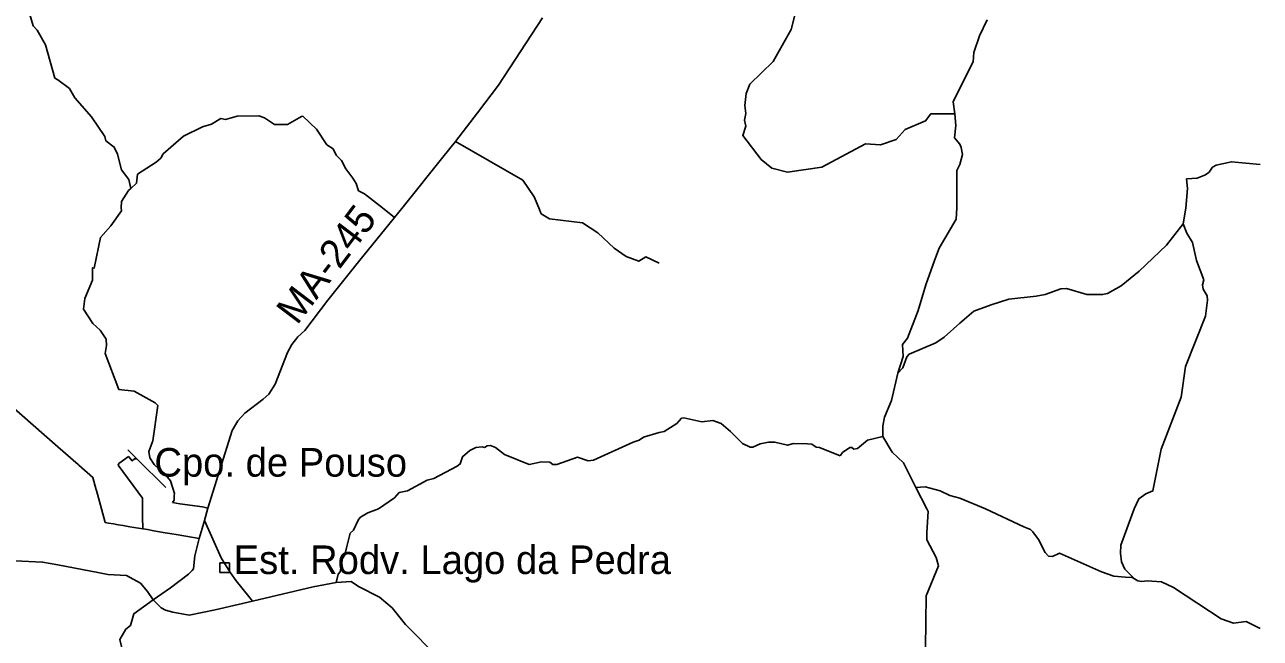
# Model space of a CAD drawing. Extents: x 332 to 501, y 9447 to 9559.
# Drawn here: x 483.56 to 500, y 9494.28 to 9502.44 of the extents above; entities that cross this region are included whole.
import ezdxf

# ---------------------------------------------------------------- set-up
doc = ezdxf.new("R2010")
doc.units = 0
for name, color, linetype in [('Level 1', 7, 'Continuous'), ('Level 13', 7, 'Continuous'), ('Level 19', 7, 'Continuous'), ('Level 2', 7, 'Continuous'), ('Level 31', 7, 'Continuous'), ('Level 4', 7, 'Continuous'), ('Level 5', 7, 'Continuous'), ('Level 51', 7, 'Continuous'), ('Level 6', 7, 'Continuous'), ('Level 8', 7, 'Continuous')]:
    doc.layers.add(name, color=color, linetype=linetype)

msp = doc.modelspace()

# ---------------------------------------------------------------- linework, layer by layer
at = {"layer": 'Level 1'}
for points in [[(485.0499, 9496.6649), (484.9306, 9496.7822)], [(485.4367, 9496.2847), (485.0499, 9496.6649)]]:
    msp.add_lwpolyline(points, dxfattribs=at)
at = {"layer": 'Level 2'}
for points in [[(490.4495, 9502.5277), (489.864, 9501.6325), (489.5831, 9501.2645)], [(489.5831, 9501.2645), (489.2899, 9500.8829)], [(489.2899, 9500.8829), (489.1226, 9500.6734)], [(489.1226, 9500.6734), (488.5953, 9500.0133)], [(484, 9496.8247), (483.1916, 9497.5294), (483.1148, 9497.7406), (483.0763, 9497.9134), (483.1084, 9498.2847), (482.7391, 9498.8538), (482.6815, 9498.9947), (482.5855, 9499.1612), (482.2526, 9499.648), (481.8249, 9499.9937)], [(488.5953, 9500.0133), (488.481, 9499.8732)], [(488.481, 9499.8732), (488, 9499.2833)], [(488, 9499.2833), (487.5929, 9498.7736)], [(487.5929, 9498.7736), (487.2845, 9498.3721), (487.1935, 9498.2871), (487.1146, 9498.1838), (487.0539, 9498.0763), (486.89, 9497.6573), (486.805, 9497.5237), (486.7295, 9497.4557)], [(486.7295, 9497.4557), (486.4886, 9497.2719)], [(486.4886, 9497.2719), (486.3934, 9497.1687), (486.3172, 9497.0424), (486.1558, 9496.5182)], [(484.2698, 9496.5875), (484, 9496.8247)], [(484.2779, 9496.5804), (484.2698, 9496.5875)], [(484.5109, 9496.2514), (484.4653, 9496.4157), (484.2779, 9496.5804)], [(485.1268, 9496.0355), (485.126, 9496.143), (484.803, 9496.5781)], [(486.1558, 9496.5181), (485.9973, 9496.0064)], [(486.1558, 9496.5182), (486.1558, 9496.5181)], [(484.5137, 9496.2414), (484.5109, 9496.2514)], [(484.5807, 9496), (484.5137, 9496.2414)], [(485.1271, 9496), (485.1268, 9496.0355)], [(484.6314, 9495.8174), (484.5807, 9496)], [(485.1272, 9495.9871), (485.1271, 9496)], [(485.1279, 9495.898), (485.1272, 9495.9871)], [(485.1293, 9495.7329), (485.1279, 9495.898)], [(485.9973, 9496.0064), (485.9509, 9495.8445)], [(484.6314, 9495.8174), (484.6747, 9495.8089)], [(484.6747, 9495.8089), (484.7381, 9495.7981)], [(484.7381, 9495.7981), (484.802, 9495.7873)], [(484.802, 9495.7873), (484.8702, 9495.7757)], [(484.8702, 9495.7757), (484.9557, 9495.7612)], [(484.9557, 9495.7612), (485.1293, 9495.7329)], [(485.1293, 9495.7329), (485.1929, 9495.7225)], [(485.1929, 9495.7225), (485.2768, 9495.7068)], [(485.2768, 9495.7068), (485.4283, 9495.6808)], [(485.9196, 9495.738), (485.8813, 9495.6038)], [(485.9509, 9495.8445), (485.9196, 9495.738)], [(485.4283, 9495.6808), (485.4902, 9495.6703)], [(485.4902, 9495.6703), (485.6003, 9495.6516)], [(485.6003, 9495.6516), (485.8813, 9495.6038)], [(485.8813, 9495.6038), (485.8219, 9495.3743), (485.8058, 9495.2011), (485.789, 9495.1806)], [(484, 9495.2529), (483.7972, 9495.2917), (483.4254, 9495.3065), (483.2376, 9495.2991), (483.0958, 9495.2475), (482.7167, 9495.3212), (482.4994, 9495.2807), (482.3338, 9495.2107), (482.2417, 9495.1518), (482.1514, 9495.1518)], [(484.5324, 9495.1507), (484, 9495.2529)], [(484.5324, 9495.1507), (484.6628, 9495.1268), (484.9115, 9495.112), (485.099, 9495.0107), (485.1937, 9494.9)], [(485.7383, 9495.1309), (485.4985, 9494.9503)], [(485.789, 9495.1806), (485.7383, 9495.1309)], [(485.1937, 9494.9), (485.2694, 9494.7905)], [(485.4985, 9494.9503), (485.2694, 9494.7905)], [(486.5904, 9494.7694), (487.3988, 9494.9624), (487.7017, 9495.0191)], [(487.7017, 9495.0191), (487.9008, 9495.0321), (488, 9494.9683)], [(488, 9494.9683), (488.2785, 9494.8252), (488.4494, 9494.6812)], [(485.2694, 9494.7905), (485.0123, 9494.6047), (484.9653, 9494.448), (484.9026, 9494.4009), (484.8242, 9494.2599), (484.8712, 9494.0561), (484.8712, 9493.9592)], [(485.2694, 9494.7905), (485.3751, 9494.6828), (485.4312, 9494.6521)], [(486.0926, 9494.6544), (486.5904, 9494.7694)], [(485.4312, 9494.6521), (485.5304, 9494.6247)], [(485.5304, 9494.6247), (485.7464, 9494.5868), (486.0926, 9494.6544)], [(489.4927, 9493.5897), (488.6259, 9494.4616), (488.4494, 9494.6812)]]:
    msp.add_lwpolyline(points, dxfattribs=at)
at = {"layer": 'Level 4'}
for points in [[(496.2621, 9502.2879), (496.3662, 9502.5001)], [(496, 9501.594), (496.178, 9501.9439), (496.1897, 9502.0647), (496.2621, 9502.2879)], [(495.9356, 9501.2488), (495.9133, 9501.4119), (496, 9501.594)], [(496, 9500.8492), (495.9288, 9500.9329), (495.9483, 9501.0964), (495.9356, 9501.2488)], [(496.0199, 9500.8042), (496, 9500.8492)], [(496, 9500.5795), (496.0378, 9500.712), (496.0199, 9500.8042)], [(495.96, 9500), (495.96, 9500.4978), (496, 9500.5795)], [(499.0199, 9500.3871), (499.16, 9500.3953), (499.269, 9500.4421), (499.3196, 9500.4772), (499.3663, 9500.5434), (499.413, 9500.5667), (499.6154, 9500.6135), (500, 9500.5756)], [(499.01, 9499.9961), (499.0319, 9500.2576), (499.0199, 9500.3871)], [(495.6654, 9499.3026), (495.7273, 9499.4628), (495.9531, 9499.852), (495.96, 9500)], [(498.9724, 9499.7889), (499.01, 9499.9961)], [(497.9662, 9498.8626), (498.1495, 9498.9652), (498.387, 9499.1599), (498.7516, 9499.5058), (498.9724, 9499.7889)], [(495.5496, 9498.9794), (495.6654, 9499.3026)], [(495.1784, 9497.8007), (495.2485, 9498.0225), (495.2407, 9498.186), (495.3068, 9498.2677), (495.447, 9498.6376), (495.5496, 9498.9794)], [(496.4179, 9498.7101), (496.6529, 9498.786), (497.0167, 9498.8249), (497.1374, 9498.8483), (497.3476, 9498.9223), (497.4216, 9498.9302), (497.6941, 9498.8483), (497.9004, 9498.8483), (497.9662, 9498.8626)], [(496, 9498.4685), (496.1897, 9498.6263), (496.4179, 9498.7101)], [(495.6848, 9498.2073), (495.7926, 9498.2835), (496, 9498.4685)], [(495.1784, 9497.8007), (495.2437, 9497.8745), (495.2982, 9498.0187), (495.3294, 9498.0576), (495.6848, 9498.2073)], [(494.9772, 9497.1034), (495, 9497.2171), (495.0932, 9497.4393), (495.1784, 9497.8007)], [(494.9782, 9496.962), (494.9772, 9497.1034)], [(495.4171, 9496.2805), (495.2518, 9496.6105), (495.1025, 9496.7536), (494.9782, 9496.962)], [(495.5634, 9496), (495.4171, 9496.2805)], [(495.563, 9495.6858), (495.5813, 9495.9656), (495.5634, 9496)], [(485.9509, 9495.8445), (486.172, 9495.3494)], [(495.543, 9494.1488), (495.5533, 9494.8413), (495.7181, 9495.2394), (495.687, 9495.3514), (495.5627, 9495.5861), (495.563, 9495.6858)], [(486.172, 9495.3494), (486.2237, 9495.2673)], [(486.2237, 9495.2673), (486.2966, 9495.1494)], [(486.2966, 9495.1494), (486.3702, 9495.0437)], [(486.3702, 9495.0437), (486.5403, 9494.8325)], [(486.5403, 9494.8325), (486.5904, 9494.7694)]]:
    msp.add_lwpolyline(points, dxfattribs=at)
at = {"layer": 'Level 5'}
for points in [[(484, 9501.702), (483.9605, 9501.7257), (483.8357, 9502.1698), (483.7247, 9502.3641), (483.6693, 9502.4196), (483.6276, 9502.5722)], [(484.9698, 9500.2594), (484.9452, 9500.3796), (484.8481, 9500.5045), (484.7926, 9500.7127), (484.751, 9500.8098), (484.6401, 9500.8931), (484.6262, 9500.9486), (484.4459, 9501.2123), (484.224, 9501.4621), (484.1547, 9501.5869), (484, 9501.702)], [(484.9698, 9500.2594), (485.0457, 9500.3303), (485.0596, 9500.4483), (485.3092, 9500.6078), (485.3716, 9500.6633), (485.3994, 9500.7189), (485.6698, 9500.9548), (485.9264, 9501.0797), (486.0443, 9501.1144), (486.1691, 9501.1907), (486.2315, 9501.1768), (486.384, 9501.2184), (486.6753, 9501.2254), (486.7516, 9501.1976), (486.8833, 9501.1074), (487.0567, 9501.1074), (487.2419, 9501.2158)], [(487.2419, 9501.2158), (487.2578, 9501.2184), (487.4415, 9501.0484), (487.5802, 9500.8403), (487.6634, 9500.7848), (487.705, 9500.7015), (487.7744, 9500.6321), (487.8299, 9500.5211), (487.9269, 9500.3962), (487.9685, 9500.3268), (488, 9500.2279)], [(489.2899, 9500.8829), (490.1857, 9500.3692), (490.3388, 9500.1453), (490.4001, 9500)], [(484.8409, 9500), (484.8446, 9500.0874), (484.9417, 9500.2332)], [(484.9417, 9500.2332), (484.9698, 9500.2594)], [(488, 9500.2279), (488.0795, 9500.1881), (488.3192, 9500)], [(485.2617, 9496.9022), (485.3319, 9497.3723), (485.2955, 9497.4088), (485.0155, 9497.5635), (484.8126, 9497.5877), (484.6289, 9498.0627), (484.6479, 9498.172), (484.641, 9498.2565), (484.563, 9498.3762), (484.4659, 9498.4612), (484.3394, 9498.652), (484.3584, 9498.7971), (484.459, 9499.0377), (484.4607, 9499.2042), (484.484, 9499.1993), (484.5672, 9499.6087), (484.7059, 9499.7613), (484.8446, 9499.9626), (484.8409, 9500)], [(488.3192, 9500), (488.481, 9499.8732)], [(490.4001, 9500), (490.4327, 9499.9227), (490.5425, 9499.8559), (490.9825, 9499.8034), (491.1845, 9499.6686), (491.4029, 9499.4644), (491.5635, 9499.3547), (491.7288, 9499.2913), (491.8248, 9499.3485), (492, 9499.2654)], [(498.681, 9496.794), (498.947, 9497.485), (499.003, 9497.893), (499.271, 9498.56), (499.299, 9498.773), (499.291, 9498.829), (499.242, 9498.92), (499.229, 9498.978), (499.247, 9499.046), (499.149, 9499.299), (499.097, 9499.541), (499.021, 9499.666), (498.9724, 9499.7889)], [(492.9501, 9497.0262), (492.824, 9497.1337), (492.7142, 9497.1757), (492.5695, 9497.1547), (492.3289, 9497.2107), (492.2986, 9497.2061), (492.2379, 9497.1337), (492.0662, 9497.0269), (492, 9497.0126)], [(492, 9497.0126), (491.7907, 9496.9498), (491.7346, 9496.9101), (491.6553, 9496.8867), (491.1268, 9496.6461), (491.0567, 9496.6367), (490.9166, 9496.6881), (490.6388, 9496.59), (490.5874, 9496.5876), (490.5477, 9496.618), (490.4333, 9496.6227), (490.2721, 9496.59), (489.9452, 9496.7232), (489.8238, 9496.8166), (489.7561, 9496.84), (489.7141, 9496.8376), (489.6777, 9496.8123)], [(492.9501, 9497.0262), (493.1083, 9496.8673), (493.2129, 9496.8182), (493.2489, 9496.8182), (493.3438, 9496.864), (493.455, 9496.8837), (493.54, 9496.8837), (493.7068, 9496.8444), (493.7886, 9496.8673), (493.975, 9496.864), (494.0306, 9496.8575), (494.0895, 9496.8182), (494.1352, 9496.815), (494.4117, 9496.7058)], [(485.2617, 9496.9022), (485.2088, 9496.7594), (485.2254, 9496.6775)], [(494.4117, 9496.7058), (494.4416, 9496.7502), (494.5364, 9496.8157), (494.5659, 9496.8157), (494.592, 9496.7928), (494.6411, 9496.8026), (494.7752, 9496.9106), (494.9782, 9496.962)], [(484.811, 9496.6009), (484.939, 9496.693), (484.988, 9496.638), (485.0214, 9496.6656), (485.0499, 9496.6649)], [(489.6777, 9496.8123), (489.6477, 9496.8236), (489.5636, 9496.8166), (489.4796, 9496.7746), (489.3862, 9496.6904), (489.3535, 9496.597), (489.3138, 9496.5643), (489.0032, 9496.4031), (488.9122, 9496.382), (488.653, 9496.2395), (488.5432, 9496.2161), (488.4778, 9496.1437), (488.265, 9496)], [(498.322, 9496), (498.383, 9496.134), (498.477, 9496.197), (498.572, 9496.237), (498.681, 9496.794)], [(484.803, 9496.5781), (484.811, 9496.6009)], [(485.3488, 9496.5245), (485.2827, 9496.5865), (485.2254, 9496.6775)], [(485.3488, 9496.5245), (485.4203, 9496.4685), (485.4996, 9496.3732), (485.5507, 9496.2039)], [(485.5507, 9496.2039), (485.5483, 9496.175)], [(495.4171, 9496.2805), (495.5387, 9496.2905), (495.7415, 9496.2381), (495.869, 9496.1759), (496, 9496.1395)], [(485.5483, 9496.175), (485.5472, 9496.114), (485.5252, 9496.0814)], [(496, 9496.1395), (496.3415, 9496)], [(488.265, 9496), (488.1263, 9495.9463), (488.0259, 9495.8903), (488, 9495.8568)], [(496.3415, 9496), (496.8519, 9495.7606)], [(498.3264, 9495.0679), (498.196, 9495.195), (498.153, 9495.295), (498.142, 9495.411), (498.145, 9495.516), (498.322, 9496)], [(488, 9495.8568), (487.9325, 9495.715), (487.8905, 9495.6753), (487.8391, 9495.479)], [(496.8519, 9495.7606), (496.9418, 9495.7243), (496.9745, 9495.6949), (497.0497, 9495.5901), (497.138, 9495.4167), (497.1838, 9495.3676), (497.2362, 9495.3643), (497.3277, 9495.4102), (497.8859, 9495.1614), (498.0494, 9495.1025), (498.2072, 9495.0921)], [(487.8391, 9495.479), (487.8181, 9495.3879), (487.7877, 9495.3365), (487.7575, 9495.1618), (487.7318, 9495.1291), (487.7017, 9495.0191)], [(498.2072, 9495.0921), (498.2947, 9495.0862), (498.3264, 9495.0679)], [(498.3264, 9495.0679), (498.3721, 9495.0404), (498.4244, 9495.0338), (498.4964, 9495.0436), (498.6861, 9495.0305), (498.8431, 9494.952), (499.4776, 9494.5364), (499.6456, 9494.4766)], [(499.6456, 9494.4766), (499.8108, 9494.5009), (500, 9494.4072)]]:
    msp.add_lwpolyline(points, dxfattribs=at)
at = {"layer": 'Level 51'}
msp.add_lwpolyline([(486.1566, 9495.2789), (486.2816, 9495.2789), (486.2816, 9495.1539), (486.1566, 9495.1539)], close=True, dxfattribs=at)
at = {"layer": 'Level 6'}
for points in [[(493.7589, 9502.3713), (493.8073, 9502.5621)], [(495.9356, 9501.2488), (495.6156, 9501.2488), (495.5461, 9501.1584), (495.2754, 9501.0439), (495.1566, 9500.908), (494.9479, 9500.8384), (494.7462, 9500.8523), (494.1637, 9500.5438), (493.7098, 9500.4767), (493.5, 9500.5288), (493.3566, 9500.6454), (493.1126, 9500.9638), (493.1529, 9501.0849), (493.1352, 9501.1688), (493.1565, 9501.2539), (493.1419, 9501.3629), (493.1605, 9501.5211), (493.2084, 9501.6447), (493.5198, 9501.9489), (493.7589, 9502.3713)]]:
    msp.add_lwpolyline(points, dxfattribs=at)
at = {"layer": 'Level 8'}
for points in [[(485.5252, 9496.0814), (485.6237, 9496.0672)], [(485.6237, 9496.0672), (485.9234, 9496.0266)], [(485.9234, 9496.0266), (485.9973, 9496.0064)]]:
    msp.add_lwpolyline(points, dxfattribs=at)

# ---------------------------------------------------------------- texts
at = {"layer": 'Level 13'}
msp.add_text('Cpo. de Pouso', height=0.38, dxfattribs=at).set_placement((485.2843, 9496.4271))
at = {"layer": 'Level 19'}
msp.add_text('Est. Rodv. Lago da Pedra', height=0.38, dxfattribs=at).set_placement((486.3392, 9495.1319))
at = {"layer": 'Level 31'}
msp.add_text('MA-245', height=0.38, rotation=52.82931, dxfattribs=at).set_placement((487.1835, 9498.4312))

doc.saveas('drawing.dxf')
